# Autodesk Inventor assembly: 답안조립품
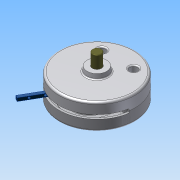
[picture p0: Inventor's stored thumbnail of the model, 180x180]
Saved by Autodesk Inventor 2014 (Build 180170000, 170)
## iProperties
Created: 2015-06
Part Number: 답안조립품
Document SubType Name: Assembly
Designer: Administrator
Author: Administrator
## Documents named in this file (9)
- C:\Documents and Settings\Administrator\바탕 화면\450631V1025\답안조립품.iam
- C:\Documents and Settings\Administrator\바탕 화면\450631V1025\1-본체.ipt
- C:\Documents and Settings\Administrator\바탕 화면\450631V1025\베어링62_22.ipt
- C:\Documents and Settings\Administrator\바탕 화면\450631V1025\덮개.ipt
- C:\Documents and Settings\Administrator\바탕 화면\450631V1025\축.ipt
- C:\Documents and Settings\Administrator\바탕 화면\450631V1025\멈춤링.ipt
- C:\Documents and Settings\Administrator\바탕 화면\450631V1025\슬라이더.ipt
- C:\Documents and Settings\Administrator\바탕 화면\450631V1025\평행핀.ipt
- C:\Documents and Settings\Administrator\바탕 화면\450631V1025\슬라이더2.ipt
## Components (6 placed, 4 different names)
1. 1-본체:1
2. KS B 2023 62/22 - 22 x 50 x 14:1
3. KS B 2023 62/22 - 22 x 50 x 14:2
4. KS B 1336 22 x 1.2:1
5. KS B 1336 22 x 1.2:2
6. KS B 1320 B B 5 x  20:1
